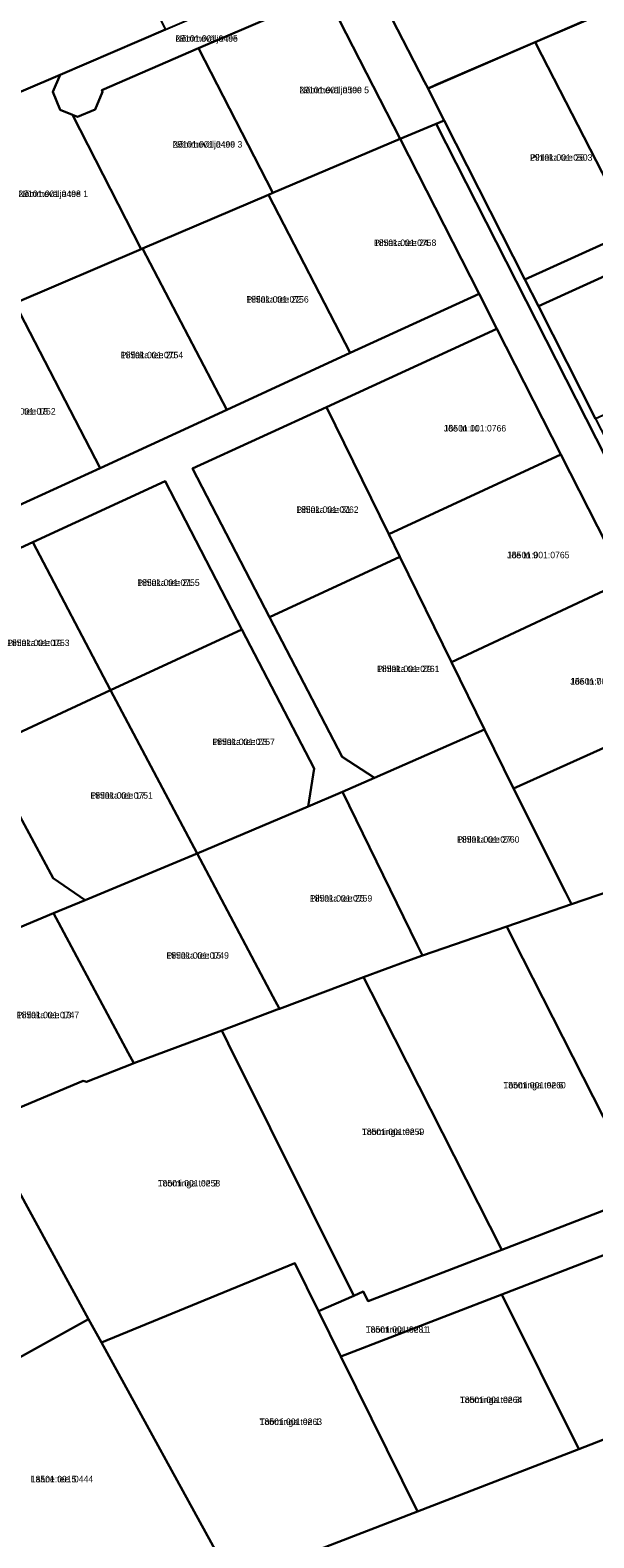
# Model space of a CAD drawing. Extents: x 660838 to 697091, y 6455678 to 6479886.
# Drawn here: x 663753.8 to 663884.8, y 6468601.6 to 6468951.8 of the extents above; entities that cross this region are included whole.
import ezdxf

# ---------------------------------------------------------------- set-up
doc = ezdxf.new("R2010")
doc.units = 0
for name, color, linetype in [('L_AADRESS', 7, 'Continuous'), ('PIIR', 7, 'Continuous'), ('TUNNUS', 7, 'Continuous')]:
    doc.layers.add(name, color=color, linetype=linetype)

msp = doc.modelspace()

# ---------------------------------------------------------------- linework, layer by layer
at = {"layer": 'PIIR'}
for points in [[(663734.77, 6468984.63), (663762.57, 6468996.15), (663764.4, 6468992.6), (663785.23, 6468951.96), (663760.77, 6468941.45), (663743.64, 6468934.13), (663735.47, 6468980.66)], [(663832.86, 6468964.21), (663876.9, 6468983.2), (663888.56, 6468960.35), (663890.16, 6468957.21), (663871.12, 6468949), (663848.09, 6468939.06), (663846.26, 6468938.27), (663845.42, 6468939.76)], [(663785.23, 6468951.96), (663819.28, 6468966.57), (663822.48, 6468960.32), (663792.95, 6468947.59), (663770.45, 6468937.86), (663770.59, 6468937.45), (663768.94, 6468933.36), (663764.84, 6468931.67), (663763.65, 6468932.16), (663760.77, 6468933.32), (663759.06, 6468937.44), (663760.77, 6468941.45)], [(663871.12, 6468949), (663899.39, 6468961.19), (663901.34, 6468957.42), (663921.69, 6468917.98), (663893.65, 6468905.19), (663872.66, 6468945.99)], [(663792.95, 6468947.59), (663822.48, 6468960.32), (663839.78, 6468926.58), (663810.2, 6468913.97)], [(663977.4, 6468943.3), (663995.7, 6468951.62), (663997.73, 6468945.09), (663957.84, 6468926.75), (663914.3, 6468906.92), (663871.95, 6468887.65), (663868.76, 6468893.88), (663893.65, 6468905.19), (663921.69, 6468917.98), (663949.78, 6468930.77)], [(663770.45, 6468937.86), (663792.95, 6468947.59), (663810.2, 6468913.97), (663809.22, 6468913.54), (663779.88, 6468901.05), (663779.64, 6468900.95), (663763.65, 6468932.16), (663764.84, 6468931.67), (663768.94, 6468933.36), (663770.59, 6468937.45)], [(663846.26, 6468938.27), (663871.12, 6468949), (663872.66, 6468945.99), (663893.65, 6468905.19), (663868.76, 6468893.88), (663849.99, 6468930.8), (663847.49, 6468935.66)], [(663743.64, 6468934.13), (663760.77, 6468941.45), (663759.06, 6468937.44), (663760.77, 6468933.32), (663763.65, 6468932.16), (663779.64, 6468900.95), (663750.22, 6468888.4), (663725.98, 6468878.05), (663723.87, 6468882.46), (663722.52, 6468885.28), (663750.6, 6468897.35), (663749.54, 6468899.66)], [(663839.78, 6468926.58), (663848.16, 6468930.06), (663929.57, 6468770.03), (663930.99, 6468767.26), (663922.49, 6468764.13), (663921.18, 6468766.64), (663907.21, 6468794.16), (663892.06, 6468823.9), (663877.12, 6468853.25), (663862.26, 6468882.43), (663858.13, 6468890.52)], [(663930.99, 6468767.26), (663929.57, 6468770.03), (663848.16, 6468930.06), (663849.99, 6468930.8), (663868.76, 6468893.88), (663871.95, 6468887.65), (663885.2, 6468861.54), (663898.53, 6468835.48), (663901.69, 6468829.23), (663914.85, 6468803.35), (663927.98, 6468777.46), (663931.12, 6468771.17), (663947.62, 6468738.59), (663964.06, 6468706.03), (663967.19, 6468699.73), (663976.47, 6468681.04), (663986.46, 6468661.45), (664006.4, 6468621.58), (664011.82, 6468610.76), (664010.85, 6468610.16), (663961.88, 6468706.49), (663931.96, 6468765.32)], [(663809.22, 6468913.54), (663810.2, 6468913.97), (663839.78, 6468926.58), (663858.13, 6468890.52), (663828.18, 6468876.84)], [(663779.88, 6468901.05), (663809.22, 6468913.54), (663828.18, 6468876.84), (663799.48, 6468863.6)], [(663871.95, 6468887.65), (663914.3, 6468906.92), (663927.56, 6468880.86), (663885.2, 6468861.54)], [(663750.22, 6468888.4), (663779.64, 6468900.95), (663779.88, 6468901.05), (663799.48, 6468863.6), (663770.09, 6468850.07)], [(663720.37, 6468875.68), (663725.98, 6468878.05), (663750.22, 6468888.4), (663770.09, 6468850.07), (663740.2, 6468836.43)], [(663822.64, 6468864.23), (663862.26, 6468882.43), (663877.12, 6468853.25), (663837.11, 6468834.72)], [(663791.55, 6468849.95), (663822.64, 6468864.23), (663837.11, 6468834.72), (663839.69, 6468829.46), (663809.43, 6468815.47)], [(663837.11, 6468834.72), (663877.12, 6468853.25), (663892.06, 6468823.9), (663851.67, 6468805.02), (663839.69, 6468829.46)], [(663754.42, 6468832.89), (663785.17, 6468847.01), (663802.96, 6468812.59), (663772.49, 6468798.52)], [(663724.42, 6468819.11), (663754.42, 6468832.89), (663772.49, 6468798.52), (663742.98, 6468784.76)], [(663809.43, 6468815.47), (663839.69, 6468829.46), (663851.67, 6468805.02), (663859.39, 6468789.33), (663833.83, 6468778.11), (663826.32, 6468782.99)], [(663851.67, 6468805.02), (663892.06, 6468823.9), (663907.21, 6468794.16), (663866.11, 6468775.67), (663859.39, 6468789.33)], [(663772.49, 6468798.52), (663802.96, 6468812.59), (663819.83, 6468780.27), (663818.41, 6468771.46), (663792.65, 6468760.54)], [(663742.98, 6468784.76), (663772.49, 6468798.52), (663792.65, 6468760.54), (663766.6, 6468749.73), (663759.16, 6468754.82)], [(663878.17, 6468751.6), (663866.11, 6468775.67), (663907.21, 6468794.16), (663921.18, 6468766.64), (663922.49, 6468764.13), (663922.59, 6468763.86), (663920.56, 6468762.86), (663897.97, 6468755.08), (663879.62, 6468748.76)], [(663826.38, 6468774.84), (663833.83, 6468778.11), (663859.39, 6468789.33), (663866.11, 6468775.67), (663878.17, 6468751.6), (663879.62, 6468748.76), (663864.55, 6468743.57), (663844.94, 6468736.82), (663843.71, 6468739.33)], [(663792.65, 6468760.54), (663818.41, 6468771.46), (663826.38, 6468774.84), (663843.71, 6468739.33), (663844.94, 6468736.82), (663841.31, 6468735.57), (663831.25, 6468731.8), (663811.72, 6468724.49), (663810.21, 6468727.32)], [(663759.25, 6468746.68), (663766.6, 6468749.73), (663792.65, 6468760.54), (663810.21, 6468727.32), (663811.72, 6468724.49), (663811.17, 6468724.28), (663798.31, 6468719.47), (663777.9, 6468711.83), (663776.61, 6468714.25)], [(663865.99, 6468740.73), (663864.55, 6468743.57), (663879.62, 6468748.76), (663897.97, 6468755.08), (663899.05, 6468752.96), (663929.11, 6468693.85), (663896.27, 6468681.19)], [(663742.64, 6468697.91), (663733.91, 6468713.56), (663723.79, 6468731.86), (663751.52, 6468743.45), (663759.25, 6468746.68), (663776.61, 6468714.25), (663777.9, 6468711.83), (663777.75, 6468711.77), (663766.9, 6468707.5), (663766.15, 6468707.76)], [(663863.44, 6468668.53), (663833.02, 6468728.32), (663831.25, 6468731.8), (663841.31, 6468735.57), (663844.94, 6468736.82), (663864.55, 6468743.57), (663865.99, 6468740.73), (663896.27, 6468681.19)], [(663799.8, 6468716.38), (663798.31, 6468719.47), (663811.17, 6468724.28), (663811.72, 6468724.49), (663831.25, 6468731.8), (663833.02, 6468728.32), (663863.44, 6468668.53), (663832.32, 6468656.54), (663831.18, 6468658.79), (663828.99, 6468657.82)], [(663742.64, 6468697.91), (663766.15, 6468707.76), (663766.9, 6468707.5), (663777.75, 6468711.77), (663777.9, 6468711.83), (663798.31, 6468719.47), (663799.8, 6468716.38), (663828.99, 6468657.82), (663820.81, 6468654.22), (663815.27, 6468665.42), (663770.39, 6468646.95), (663767.34, 6468652.41), (663750.34, 6468683.68)], [(663826, 6468643.72), (663820.81, 6468654.22), (663828.99, 6468657.82), (663831.18, 6468658.79), (663832.32, 6468656.54), (663863.44, 6468668.53), (663896.27, 6468681.19), (663929.11, 6468693.85), (663953.19, 6468703.12), (663961.88, 6468706.49), (664010.85, 6468610.16), (664011.97, 6468594.44), (664008.93, 6468591.97), (664004.79, 6468600.1), (663975.18, 6468658.35), (663966.33, 6468675.78), (663956.97, 6468694.2), (663938.59, 6468687.11), (663900.86, 6468672.57), (663863.38, 6468658.13)], [(663706.77, 6468659.47), (663750.34, 6468683.68), (663767.34, 6468652.41), (663724.05, 6468628.36), (663713.8, 6468646.8)], [(663863.38, 6468658.13), (663900.86, 6468672.57), (663918.76, 6468636.59), (663888.66, 6468625.04), (663881.29, 6468622.19)], [(663770.39, 6468646.95), (663815.27, 6468665.42), (663820.81, 6468654.22), (663826, 6468643.72), (663843.84, 6468607.7), (663800.86, 6468591.18), (663798.47, 6468595.74)], [(663826, 6468643.72), (663863.38, 6468658.13), (663881.29, 6468622.19), (663843.84, 6468607.7)], [(663713.8, 6468646.8), (663724.05, 6468628.36), (663767.34, 6468652.41), (663770.39, 6468646.95), (663798.47, 6468595.74), (663751.8, 6468583.46), (663734.19, 6468606.75), (663719.68, 6468625.93), (663709.43, 6468644.37)], [(663816.98, 6468561.02), (663800.86, 6468591.18), (663843.84, 6468607.7), (663881.29, 6468622.19), (663888.66, 6468625.04), (663910.1, 6468575.16), (663943.56, 6468586.75), (663964.17, 6468593.24), (663989.12, 6468599.37), (664004.79, 6468600.1), (664008.93, 6468591.97), (664004.24, 6468594.14), (663995.43, 6468594.42), (663981.79, 6468592.26), (663962.02, 6468586.4), (663918.09, 6468572.36), (663869.44, 6468565.97), (663827.01, 6468555.9), (663824.66, 6468561.08), (663817.81, 6468559.34)]]:
    msp.add_lwpolyline(points, close=True, dxfattribs=at)
for points in [[(663832.86, 6468964.21), (663845.42, 6468939.76), (663846.26, 6468938.27), (663847.49, 6468935.66), (663849.99, 6468930.8), (663848.16, 6468930.06), (663839.78, 6468926.58), (663822.48, 6468960.32)], [(663740.2, 6468836.43), (663770.09, 6468850.07), (663799.48, 6468863.6), (663828.18, 6468876.84), (663858.13, 6468890.52), (663862.26, 6468882.43), (663822.64, 6468864.23), (663791.55, 6468849.95), (663809.43, 6468815.47), (663826.32, 6468782.99), (663833.83, 6468778.11), (663826.38, 6468774.84), (663818.41, 6468771.46), (663819.83, 6468780.27), (663802.96, 6468812.59), (663785.17, 6468847.01), (663754.42, 6468832.89), (663724.42, 6468819.11)], [(663742.98, 6468784.76), (663759.16, 6468754.82), (663766.6, 6468749.73), (663759.25, 6468746.68), (663751.52, 6468743.45)]]:
    msp.add_lwpolyline(points, dxfattribs=at)

# ---------------------------------------------------------------- texts
at = {"layer": 'L_AADRESS'}
for s, p in [('Nõmmevälja tee', (663787.56, 6468949.12)), ('Nõmmevälja tee 5', (663816.37, 6468937.14)), ('Nõmmevälja tee 3', (663786.93, 6468924.52)), ('Pihlaka tee 26', (663869.95, 6468921.46)), ('Nõmmevälja tee 1', (663751.08, 6468913.04)), ('Pihlaka tee 24', (663833.68, 6468901.66)), ('Pihlaka tee 22', (663804.03, 6468888.51)), ('Pihlaka tee 20', (663774.85, 6468875.58)), ('Pihlaka tee 18', (663745.23, 6468862.5)), ('Jõe tn 11', (663849.91, 6468858.57)), ('Pihlaka tee 31', (663815.62, 6468839.67)), ('Jõe tn 9', (663864.62, 6468829.13)), ('Pihlaka tee 21', (663778.69, 6468822.71)), ('Pihlaka tee 19', (663748.46, 6468808.73)), ('Pihlaka tee 29', (663834.41, 6468802.69)), ('Jõe tn 7', (663879.3, 6468799.79)), ('Pihlaka tee 23', (663796.16, 6468785.74)), ('Pihlaka tee 17', (663767.81, 6468773.29)), ('Pihlaka tee 27', (663853, 6468763.06)), ('Pihlaka tee 25', (663818.79, 6468749.38)), ('Pihlaka tee 15', (663785.48, 6468736.12)), ('Pihlaka tee 13', (663750.69, 6468722.29)), ('Toominga tee 6', (663863.76, 6468705.98)), ('Toominga tee 4', (663830.88, 6468695.16)), ('Toominga tee 2', (663783.46, 6468683.21)), ('Toominga tee L1', (663831.78, 6468649.23)), ('Toominga tee 3', (663853.65, 6468632.91)), ('Toominga tee 1', (663807.12, 6468627.82)), ('Laane tee 5', (663753.95, 6468614.5))]:
    msp.add_text(s, height=1.5, dxfattribs=at).set_placement(p)
at = {"layer": 'TUNNUS'}
for s, p in [('29101:001:0495', (663787.56, 6468949.12)), ('29101:001:0500', (663816.37, 6468937.14)), ('29101:001:0499', (663786.93, 6468924.52)), ('29101:001:0503', (663869.95, 6468921.46)), ('29101:001:0498', (663751.08, 6468913.04)), ('18501:001:0758', (663833.68, 6468901.66)), ('18501:001:0756', (663804.03, 6468888.51)), ('18501:001:0754', (663774.85, 6468875.58)), ('18501:001:0752', (663745.23, 6468862.5)), ('18501:001:0766', (663849.91, 6468858.57)), ('18501:001:0762', (663815.62, 6468839.67)), ('18501:001:0765', (663864.62, 6468829.13)), ('18501:001:0755', (663778.69, 6468822.71)), ('18501:001:0753', (663748.46, 6468808.73)), ('18501:001:0761', (663834.41, 6468802.69)), ('18501:001:0764', (663879.3, 6468799.79)), ('18501:001:0757', (663796.16, 6468785.74)), ('18501:001:0751', (663767.81, 6468773.29)), ('18501:001:0760', (663853, 6468763.06)), ('18501:001:0759', (663818.79, 6468749.38)), ('18501:001:0749', (663785.48, 6468736.12)), ('18501:001:0747', (663750.69, 6468722.29)), ('18501:001:0260', (663863.76, 6468705.98)), ('18501:001:0259', (663830.88, 6468695.16)), ('18501:001:0258', (663783.46, 6468683.21)), ('18501:001:0281', (663831.78, 6468649.23)), ('18501:001:0264', (663853.65, 6468632.91)), ('18501:001:0263', (663807.12, 6468627.82)), ('18501:001:0444', (663753.95, 6468614.5))]:
    msp.add_text(s, height=1.5, dxfattribs=at).set_placement(p)

doc.saveas('drawing.dxf')
